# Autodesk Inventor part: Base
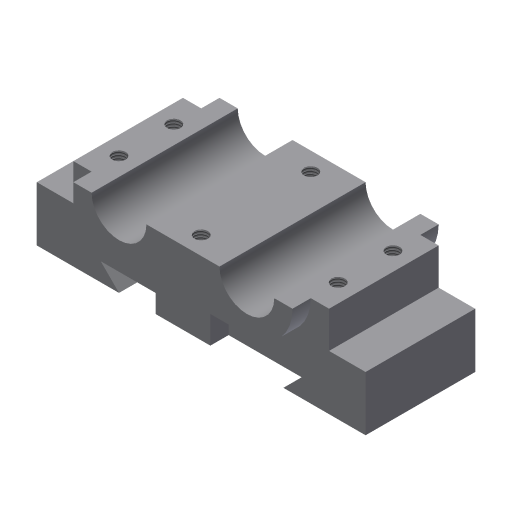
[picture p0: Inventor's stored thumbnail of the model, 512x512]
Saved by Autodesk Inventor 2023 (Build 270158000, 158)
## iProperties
Created: 2002-02
Part Number: Base
Document SubType Name: Modeling
Designer: ***
Density: 1 g/cm^3
Material: Generic
Appearance: Default
Control State: 0
Master: False
Checked Out: False
Shininess: 77.0
Length Units: 11269
Angle Units: 11279
Time Units: 11290
Mass Units: 11283
Length Display Precision: 3
Angle Display Precision: 2
Density: 0.0
Volumn: 0.0
Area: 0.0
PropertySet Name: Model Information
Author: ***
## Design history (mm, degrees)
sketch "Sketch2"
  geometry: L1 (-10.066, -1.263)-(24.934, -1.263); L2 (37.434, 11.237)-(32.434, 11.237); L3 (17.434, 11.237)-(-2.566, 11.237); L4 (-17.566, 11.237)-(-22.566, 11.237); A1 r 12.5 centre (-10.066, 11.237) between (-22.566, 11.237) and (-10.066, -1.263); A2 r 12.5 centre (24.934, 11.237) between (24.934, -1.263) and (37.434, 11.237); A3 r 7.5 centre (24.934, 11.237) between (17.434, 11.237) and (32.434, 11.237); A4 r 7.5 centre (-10.066, 11.237) between (-17.566, 11.237) and (-2.566, 11.237)
  constraints: 8 end point, 8 point on circle, 4 centre point, 3 horizontal, 3 parallel, 2 coincident, 2 equal radius, 2 tangent
  dimensions: "d0" = 12.5 radius of A1; "d1" = 7.5 radius of A4; "d2" = 35 distance of A1.centre A2.centre; "d3" = 12.5 distance between parallel lines of L3 L1
extrude "Extrusion1" new body sketch "Sketch2" stored distance "d4" = 40; taper "d5" = 0 deg
sketch "Sketch4"
  geometry: L1 (-27.566, 1.237)-(-37.566, 1.237); L2 (-37.566, 1.237)-(-37.566, -13.763); L3 (-37.566, -13.763)-(-15.066, -13.763); L4 (-15.066, -13.763)-(-20.066, -8.763); L5 (-20.066, -8.763)-(34.934, -8.763); L6 (34.934, -8.763)-(29.934, -13.763); L7 (29.934, -13.763)-(52.434, -13.763); L8 (52.434, -13.763)-(52.434, 1.237); L9 (52.434, 1.237)-(42.434, 1.237); L10 (24.934, -1.263)-(-10.066, -1.263); L11 (-17.566, 11.237)-(-22.566, 11.237) reference; L12 (37.434, 11.237)-(32.434, 11.237) reference; L13 (-22.566, 11.237)-(-27.566, 11.237); L14 (-27.566, 11.237)-(-27.566, 1.237); L15 (37.434, 11.237)-(42.434, 11.237); L16 (42.434, 11.237)-(42.434, 1.237); A1 r 12.5 centre (24.934, 11.237) between (24.934, -1.263) and (37.434, 11.237); A2 r 12.5 centre (-10.066, 11.237) between (-22.566, 11.237) and (-10.066, -1.263); A3 r 12.5 centre (24.934, 11.237) between (24.934, -1.263) and (37.434, 11.237) reference; A4 r 12.5 centre (-10.066, 11.237) between (-22.566, 11.237) and (-10.066, -1.263) reference
  constraints: 28 end point, 6 perpendicular, 5 equal length, 4 concentric, 4 parallel, 4 point on circle, 2 centre point, 2 collinear, 1 tangent
  dimensions: "d12" = 15 distance of L1.end L2.end; "d13" = 25 distance from line of L3 L11.end; "d14" = 90 distance between parallel lines of L2 L8; "d15" = 5 distance between parallel lines of L5 L7; "d16" = 22.5 distance of L2.end L3.end; "d24" = 5 distance of L12.start L15.end; "d25" = 15 distance from line of L8 L12.start
extrude "Extrusion3" join sketch "Sketch4" stored distance "d17" = 30; taper "d18" = 0 deg
sketch "Sketch5"
  geometry: L1 (-14.934, -1.263)-(0.066, -1.263); L2 (0.066, -1.263)-(0.066, -8.763); L3 (0.066, -8.763)-(-14.934, -8.763); L4 (-14.934, -8.763)-(-14.934, -1.263); L5 (10.066, -1.263)-(-24.934, -1.263) reference; 1 further point
  constraints: 8 end point, 2 parallel, 1 collinear, 1 horizontal, 1 perpendicular
  dimensions: "d19" = 7.5 distance of L1.end L2.end; "d20" = 15 distance of L2.end L3.end; "d21" = 15 distance from line of point (-29.934, -13.763) L4
extrude "Extrusion4" join sketch "Sketch5" distance "d22" = 40; taper "d23" = 0 deg
sketch "Sketch6"
  geometry: L1 (-5, -35)-(0, -35) reference; L2 (-5, -35)-(-5, -5) reference; 1 further point
  dimensions: "d26" = 7.5 distance from line of L1 point (0, -27.5); "d27" = 5 distance from line of L2 point (0, -27.5)
hole "Hole1" sketch "Sketch6" at (0, -27.5) diameter "d28" = 3.688; stored, may be unused: countersink angle "d32" = 82 deg, drill point angle "d34" = 0 deg; dims "d29" = 9, "d30" = 4, "d31" = 2, "d33" = 15
pattern_linear "Rectangular Pattern1" dims "d37" = 60, "d40" = 15
sketch "Sketch7"
  geometry: L1 (-20, -40)-(-20, -35) reference; L2 (0, -40)-(20, -40) reference; 1 further point
  dimensions: "d41" = 30 distance from line of L1 point (10, -35); "d42" = 5 distance from line of L2 point (10, -35)
hole "Hole2" sketch "Sketch7" at (10, -35) diameter "d43" = 3.688; stored, may be unused: countersink angle "d47" = 82 deg, drill point angle "d49" = 0 deg; dims "d44" = 9, "d45" = 4, "d46" = 2, "d48" = 15
pattern_linear "Rectangular Pattern2" dims "d52" = 30
body "Solid1"
